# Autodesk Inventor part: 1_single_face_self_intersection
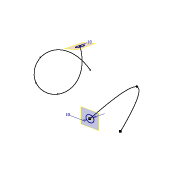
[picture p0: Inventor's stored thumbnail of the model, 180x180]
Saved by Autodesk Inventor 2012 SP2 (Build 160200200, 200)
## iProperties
Company: Autodesk, Inc.
Created: 2013-06
Part Number: 1_single_face_self_intersection
Material: Default
Document SubType Name: Modeling
Designer: Glenn Chun
Density: 1 g/cm^3
Author: Glenn Chun
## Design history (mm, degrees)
sketch "Path1"
node "Normal to Path1"
sketch "Profile1"
  geometry: C1 r 5 at (0, 0); 2 further points
  constraints: 2 coincident, 1 centre point
  dimensions: "d0" = 10 diameter of C1
sketch "Path2 (high-curvature)"
  geometry: 3 further points
  constraints: 3 other
node "Normal to Path2"
sketch "Profile2"
  geometry: C1 r 5 at (0, 0); 1 further point
  constraints: 1 centre point, 1 coincident
  dimensions: "d1" = 10 diameter of C1
